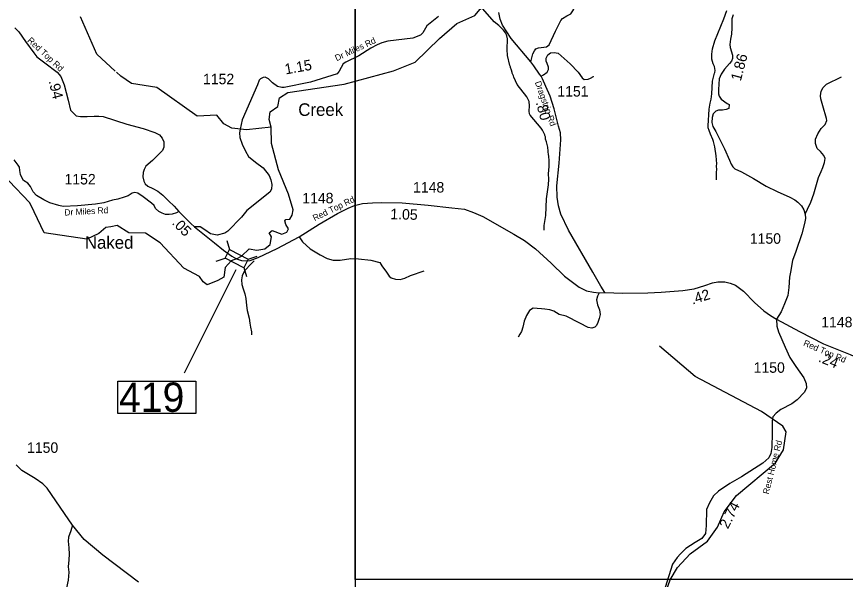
# Model space of a CAD drawing. Extents: x 1248089 to 1457196, y 820910 to 988753.
# Drawn here: x 1308985 to 1318874, y 868837 to 875551 of the extents above; entities that cross this region are included whole.
import ezdxf

# ---------------------------------------------------------------- set-up
doc = ezdxf.new("R2010")
doc.units = 0
for name, color, linetype in [('Exist Hydrographic Creek Single Shore', 7, 'Continuous'), ('Exist Hydrographic Misc Water Feature', 7, 'Continuous'), ('Exist Road Non-System Type 51', 7, 'Continuous'), ('Exist Road Secondary Structure Standard Bridge CELL', 7, 'Continuous'), ('Exist Road Secondary Structure Standard Bridge Number Label', 7, 'Continuous'), ('Exist Road Secondary Type 41 Attributed', 7, 'Continuous'), ('Exist Road Secondary Type 51 Attributed', 7, 'Continuous'), ('Exist Road Secondary Type 51 Label', 7, 'Continuous'), ('Map Preparation Inset Cut Line', 7, 'Continuous'), ('Prop GRAU CAT1 Cell', 7, 'Continuous'), ('Prop Lane Lines', 7, 'Continuous')]:
    doc.layers.add(name, color=color, linetype=linetype)

msp = doc.modelspace()

# ---------------------------------------------------------------- linework, layer by layer
at = {"layer": 'Exist Hydrographic Creek Single Shore'}
for points in [[(1312022.4, 874231.7), (1311999.3, 874324), (1312010.4, 874415.8), (1312103.4, 874479.6), (1312122.3, 874581), (1312223.3, 874644.6), (1312893.3, 874746), (1313480.4, 874905), (1313741.3, 875008.1), (1314032.4, 875289.4), (1314239.5, 875467.5), (1314450.7, 875564.2), (1314515.6, 875637.3), (1314660.8, 875736.4)], [(1312022.4, 874231.7), (1311730.4, 874198.2), (1311555.4, 874218), (1311456.3, 874269.3), (1311375.3, 874372.7), (1311141.4, 874361.1), (1310657.3, 874705.5), (1310358.3, 874754.2), (1310227.2, 874838.9), (1310176.6, 874885.9)], [(1311610.2, 872660.7), (1311668.4, 872691.6), (1311758.7, 872781.3), (1311852.4, 872764.8), (1311948.1, 872778.2), (1312009.9, 872832.8), (1312028.5, 872922.5), (1311999.6, 872971.9), (1312033.5, 872997.4), (1312148.9, 872954.1), (1312210.6, 872977.8), (1312229.2, 873019), (1312199.3, 873070.5), (1312185.9, 873114.9), (1312196.2, 873128.2), (1312244.6, 873132.4), (1312274.5, 873179.8), (1312286.8, 873245.7), (1312228.1, 873430.7), (1312110.3, 873721.1), (1312026.4, 874038), (1312022.4, 874231.7)], [(1309154.5, 873303.6), (1309141.3, 873330.9), (1308897.3, 873588.6), (1308830.3, 873606.4), (1308585.6, 873596.3), (1308575.8, 873602.6), (1308466.6, 873740.7), (1308388.7, 873762), (1308206.5, 873839.3), (1307897, 874073.3)], [(1310982.6, 872548.7), (1310698.4, 872853.2), (1310525.3, 872965.1), (1310325.4, 872969.1), (1310185.3, 873057.2), (1310111.5, 873044.2)], [(1311610.2, 872660.7), (1311545.8, 872635), (1311472.7, 872556.4), (1311459.3, 872441), (1311386.2, 872402.3), (1311258.5, 872348.8), (1311211.2, 872385.9), (1311167.9, 872451.8), (1310982.6, 872548.7)]]:
    msp.add_lwpolyline(points, dxfattribs=at)
at = {"layer": 'Exist Hydrographic Misc Water Feature'}
for points in [[(1315280.9, 873003), (1315278.4, 873059), (1315297.8, 873178.5), (1315309.4, 873378), (1315332.1, 873545.3), (1315333.9, 873609.3), (1315329.8, 873675.3), (1315338.2, 873761), (1315340, 873825), (1315335.8, 873889.1), (1315332, 873897.2), (1315322.7, 873993.5), (1315308.6, 874057.8), (1315297.4, 874090.1), (1315294.1, 874114.2), (1315286.5, 874130.4), (1315286.8, 874138.4), (1315260.4, 874195.2), (1315245.1, 874219.6), (1315113.4, 874375.4), (1315105.9, 874391.6), (1315100.7, 874423.8), (1315106.5, 874487.5), (1315101.9, 874535.6), (1315071.4, 874592.5), (1314959.6, 874739.7), (1314918, 874828.8), (1314914.5, 874844.9), (1314899.4, 874877.4), (1314899.6, 874885.4), (1314888.3, 874909.7), (1314877.2, 874942), (1314877.4, 874950), (1314869.9, 874966.2), (1314843.3, 875087), (1314839.3, 875159.1), (1314840.9, 875286.9), (1314835.8, 875319.1), (1314820.7, 875353.6), (1314793.8, 875390.3), (1314739.2, 875443.9), (1314682.5, 875489.5), (1314548.2, 875641.9)], [(1317336.6, 873603.3), (1317335.3, 873699.3), (1317338, 873723.3), (1317335.3, 873771.3), (1317338, 873795.3), (1317332.6, 873891.3), (1317315.6, 873995.8), (1317301.5, 874060.2), (1317294.1, 874084.4), (1317263.9, 874149.3), (1317249.1, 874189.7), (1317237.9, 874222), (1317234.6, 874246.1), (1317250.2, 874445.6), (1317260.3, 874517.3), (1317271.6, 874564.9), (1317281.4, 874628.6), (1317289.7, 874780.3), (1317312.3, 874875.6), (1317316.5, 874883.5), (1317319.2, 874907.4), (1317310.6, 874955.7), (1317295.5, 874988.1), (1317281.1, 875044.5), (1317280.7, 875100.4), (1317288.4, 875164.2), (1317315.1, 875259.5), (1317422.5, 875522.2), (1317457.4, 875623.2)], [(1310163.5, 874898), (1309941.3, 875104.1), (1309749.3, 875547)], [(1310111.5, 873044.2), (1310051.3, 873033.6), (1309966.3, 872963.1), (1309823.3, 872897), (1309316.3, 872969.6), (1309154.5, 873303.6)], [(1316710, 867717.5), (1316634.5, 868174.3), (1316676.5, 868531.2), (1316783.5, 868831.1), (1316869.5, 868977.1), (1317023.5, 869141.4), (1317227.5, 869294.9), (1317348.5, 869460), (1317427.5, 869642.2), (1317573.5, 869836.2), (1318041.6, 870227.3), (1318136.5, 870382.9), (1318166.6, 870599.1), (1318126.6, 870665.5), (1317872.5, 870838.1), (1317081.5, 871257.7), (1316656.4, 871617.5)]]:
    msp.add_lwpolyline(points, dxfattribs=at)
at = {"layer": 'Exist Road Non-System Type 51'}
for points in [[(1315119.2, 875008.9), (1315143.4, 875106), (1315165.3, 875142.5), (1315182.3, 875164.3), (1315213.8, 875176.5), (1315274.5, 875183.8), (1315308.5, 875191), (1315340, 875215.3), (1315415.3, 875375.6), (1315478.4, 875504.4), (1315497.8, 875528.6), (1315551.2, 875560.2), (1315596.7, 875581.4), (1315623.4, 875617.8), (1315664.7, 875695.5)], [(1315242.1, 874839.3), (1315273.6, 874853.9), (1315314.9, 874887.9), (1315331.9, 874919.5), (1315331.9, 874946.2), (1315317.3, 874989.9), (1315305.2, 875019.1), (1315302.8, 875055.5), (1315322.2, 875094.4), (1315356.1, 875116.2), (1315399.8, 875121.1), (1315445.9, 875113.8), (1315591.6, 874985.1), (1315683.8, 874887.9), (1315732.3, 874819.9), (1315756.6, 874800.5), (1315805.1, 874805.3), (1315831.8, 874815), (1315868.2, 874836.9), (1315869.1, 874841.6)], [(1318394.8, 873191.7), (1318420.6, 873255.1), (1318461.8, 873335.3), (1318495.8, 873437.3), (1318520.1, 873519.9), (1318554.1, 873629.2), (1318585.6, 873704.5), (1318605, 873750.6), (1318624.4, 873811.3), (1318631.7, 873857.5), (1318617.2, 873893.9), (1318578.3, 873940.1), (1318537.1, 873978.9), (1318515.2, 874034.8), (1318517.7, 874088.2), (1318546.8, 874153.8), (1318583.2, 874214.5), (1318631.7, 874263.1), (1318651.1, 874311.7), (1318648.7, 874336), (1318605, 874484.1), (1318580.8, 874570.2), (1318578.3, 874604.2), (1318583.2, 874662.5), (1318607.5, 874703.8), (1318648.7, 874745.1), (1318828.3, 874832.5)], [(1312355.4, 872923.5), (1312396.2, 872863.4), (1312487.2, 872779.6), (1312607.4, 872706.7), (1312691.1, 872666.7), (1312763.9, 872644.8), (1312847.7, 872644.8), (1312971.4, 872666.7), (1313066.1, 872659.4), (1313211.7, 872644.8), (1313317.3, 872615.7), (1313342.8, 872579.2), (1313397.4, 872502.7), (1313430.1, 872455.4), (1313455.6, 872433.5), (1313506.6, 872418.9), (1313561.2, 872415.3), (1313619.4, 872429.9), (1313685, 872462.6), (1313848.8, 872517.3)], [(1311818.7, 872638.8), (1311790.1, 872604.4), (1311705.9, 872515.9), (1311676.4, 872459), (1311670.1, 872408.5), (1311672.2, 872353.7), (1311686.9, 872301), (1311710.1, 872242), (1311720.6, 872189.4), (1311729, 872105.1), (1311737.5, 872044), (1311758.5, 871951.3), (1311766.9, 871892.4), (1311777.5, 871843.9), (1311790.1, 871791.2), (1311790.1, 871753.3)], [(1315935.3, 872256.4), (1315915.4, 872214.9), (1315903.1, 872173.5), (1315916.9, 872113.5), (1315941.5, 872050.5), (1315946.1, 871996.7), (1315935.3, 871947.6), (1315921.5, 871901.5), (1315904.6, 871864.6), (1315883.1, 871844.6), (1315847.8, 871832.3), (1315804.8, 871843.1), (1315705, 871895.3), (1315542.2, 871976.8), (1315457.8, 871998.3), (1315394.8, 872036.7), (1315345.7, 872050.5), (1315288.9, 872061.3), (1315247.4, 872065.9), (1315196.8, 872069), (1315147.6, 872073.6), (1315103.1, 872045.9), (1315069.3, 871986), (1315043.2, 871916.8), (1315026.3, 871844.6), (1315007.9, 871793.9), (1314991, 871763.2), (1314968, 871726.3)], [(1309653.7, 869485.8), (1309633.1, 869416.2), (1309603.1, 869340.1), (1309599.1, 869292.1), (1309607.1, 869212), (1309613.1, 869138), (1309609.1, 869071.9), (1309599.1, 868987.9), (1309607.1, 868921.8), (1309601.1, 868829.7), (1309569.1, 868681.6), (1309571.1, 868545.5), (1309561.3, 868444.7), (1309555.3, 868382.7), (1309537.3, 868300.6), (1309525.3, 868270.6), (1309515.3, 868258.6)]]:
    msp.add_lwpolyline(points, dxfattribs=at)
at = {"layer": 'Exist Road Secondary Structure Standard Bridge CELL'}
for p, q in [((1311492.9, 872879.3), (1311527.4, 872771.5)), ((1311747.5, 872657.4), (1311855.3, 872691.9)), ((1311366.5, 872634.1), (1311474.3, 872668.6)), ((1311695.6, 872556.8), (1311730.1, 872449))]:
    msp.add_line(p, q, dxfattribs=at)
msp.add_lwpolyline([(1311527.4, 872771.5), (1311747.7, 872657.9), (1311694.7, 872555), (1311474.3, 872668.6)], close=True, dxfattribs=at)
at = {"layer": 'Exist Road Secondary Structure Standard Bridge Number Label'}
msp.add_line((1311600, 872528.6), (1310984.4, 871297.5), dxfattribs=at)
msp.add_lwpolyline([(1310194, 871199.9), (1311123, 871199.9), (1311123, 870815.7), (1310194, 870815.7)], close=True, dxfattribs=at)
at = {"layer": 'Exist Road Secondary Type 41 Attributed'}
for points in [[(1314017.3, 875553), (1313878.7, 875440.2), (1313831.7, 875356.6), (1313806, 875328.8), (1313711.8, 875292.4), (1313416.5, 875256), (1313343.7, 875236.7), (1313285.9, 875215.3), (1313211.8, 875173.3), (1313068.4, 875081.2), (1312914.3, 875008.4), (1312880, 874987), (1312835.1, 874901.3), (1312811.6, 874867), (1312493.7, 874769.2), (1312179, 874702.8), (1312149.1, 874702.8), (1312099.9, 874715.6), (1312037.8, 874760.6), (1311990.7, 874807.7), (1311952.2, 874827), (1311926.5, 874822.7), (1311896.5, 874809.8), (1311879.4, 874790.6), (1311860.2, 874737), (1311678.3, 874320.6), (1311653.8, 874206.9), (1311646.2, 874162.1), (1311650.5, 874106.4), (1311676.2, 874027.1), (1311714.7, 873943.6), (1311753.2, 873881.5), (1311834.4, 873813.9), (1311926.4, 873747.5), (1311999.2, 873655.4), (1312020.6, 873604), (1312031.3, 873548.3), (1312027, 873490.5), (1312007.7, 873456.2), (1311734.4, 873238.3), (1311670.2, 873159.1), (1311505.4, 872992), (1311471.2, 872966.3), (1311377, 872942.7), (1311297.8, 872957.7), (1311231.5, 873007), (1311173.7, 873043.4), (1311109.5, 873043.4)], [(1310921.8, 873226), (1310893.3, 873208.4), (1310843.5, 873193.3), (1310805.5, 873187.8), (1310763.4, 873190.6), (1310722.8, 873206.9), (1310683.4, 873225.9), (1310644.1, 873261.1), (1310625.1, 873296.4), (1310595.2, 873325), (1310494.9, 873402.3), (1310433.8, 873443.1), (1310395.9, 873452.6), (1310362.5, 873443.1), (1310316.4, 873413.3), (1310270.3, 873395.6), (1310191.6, 873372.6), (1310127.9, 873361.7), (1310026.1, 873327.8), (1309927.1, 873312.8), (1309713.5, 873293.7), (1309542.6, 873287), (1309491, 873297.8), (1309381.2, 873329), (1309309.3, 873364.3), (1309223.8, 873417.3), (1309184.5, 873459.4), (1309153.3, 873524.5), (1309118.3, 873561.8), (1309068.1, 873597.1), (1309047.8, 873629.6), (1309032.9, 873666.3), (1309026.1, 873713.8), (1309020.6, 873754.5), (1309005.7, 873779), (1308956.9, 873842.8)], [(1318052.7, 871939.5), (1318056.1, 871858.6), (1318074.3, 871790.9), (1318156.1, 871605.9), (1318209.2, 871484.8), (1318281.8, 871375.8), (1318379.1, 871240.5), (1318405.5, 871174.5), (1318408.8, 871123.3), (1318385.7, 871072.1), (1318298.3, 870979.7), (1318232.8, 870931.1), (1318104.2, 870865.1), (1318048.1, 870820.5), (1318006.9, 870774.3), (1317998.6, 870729.7)], [(1317998.6, 870729.7), (1317998.6, 870583.5), (1317995.3, 870410.2), (1317985.4, 870337.6), (1317959, 870288.1), (1317888.6, 870224.2), (1317634.6, 870059.2), (1317496, 869981.6), (1317359.6, 869890), (1317298.5, 869832.2), (1317252.4, 869749.7), (1317217.7, 869668.8), (1317214.4, 869480.6), (1317203.3, 869382.6), (1317160.4, 869324.8), (1317082.9, 869275.3), (1316969.1, 869204.3), (1316906.4, 869143.3), (1316866.9, 869097), (1316812.4, 869019.5), (1316725.4, 868740.2)], [(1310441.6, 868803.4), (1310014.9, 869126), (1309792.2, 869312.5), (1309653.7, 869485.8), (1309556.8, 869621.9), (1309349, 869924), (1309299.5, 869978.4), (1309205.5, 870039.5), (1309047.2, 870136.9), (1308981.2, 870204.6)]]:
    msp.add_lwpolyline(points, dxfattribs=at)
at = {"layer": 'Exist Road Secondary Type 51 Attributed'}
for points in [[(1316003.9, 872258.2), (1315956.7, 872335.8), (1315860.3, 872500.7), (1315569.6, 873002.8), (1315479.8, 873195.5), (1315449.8, 873291.9), (1315434.8, 873394.7), (1315432.6, 873532.9), (1315460.5, 873800.6), (1315477.6, 874079.1), (1315473.3, 874164.7), (1315452, 874242.8), (1315398.5, 874448.4), (1315349.5, 874599.5), (1315300.3, 874717.3), (1315259.6, 874809.4), (1315242.1, 874839.3), (1315223.2, 874865.1), (1315154.7, 874963.6), (1315119.2, 875008.9), (1314885.4, 875290.1), (1314782.7, 875448.6), (1314754.8, 875521.4), (1314737.7, 875598.5)], [(1317534, 875571.9), (1317517.3, 875524.3), (1317517.3, 875416.7), (1317515.9, 875339.8), (1317504.7, 875279.7), (1317496.3, 875216.8), (1317499.2, 875182.6), (1317525.7, 875091.8), (1317525.7, 875051.2), (1317514.5, 875020.5), (1317489.4, 874991.1), (1317432.1, 874922.6), (1317390.2, 874863.9), (1317369.3, 874808), (1317359.5, 874682), (1317359.5, 874627.5), (1317366.5, 874600.9), (1317393.1, 874567.4), (1317462.9, 874512.9), (1317485.3, 874500.3), (1317481.1, 874455.6), (1317451.7, 874441.6), (1317405.6, 874436), (1317360.9, 874436), (1317327.4, 874423.4), (1317296.7, 874391.3), (1317282.7, 874346.5), (1317279.9, 874286.4), (1317292.5, 874238.9), (1317327.3, 874179.5), (1317432, 873974), (1317492.1, 873838.4), (1317510.2, 873790.9), (1317531.2, 873758.7), (1317556.3, 873735), (1317635.2, 873697.9), (1317776.3, 873621), (1317927.2, 873528.8), (1318059.6, 873462.1), (1318209, 873396.4), (1318269.1, 873364.2), (1318308.2, 873337.7), (1318351.5, 873294.3), (1318379.4, 873246.2), (1318394.8, 873191.7), (1318396.2, 873141.3), (1318387.8, 873081.2), (1318352.9, 872958.2), (1318281.6, 872747.1), (1318242.7, 872642), (1318220.3, 872503.6), (1318205, 872442.1), (1318200.8, 872317.7), (1318185.4, 872225.4), (1318147.7, 872124), (1318108.6, 872029), (1318052.7, 871939.5)], [(1308962.9, 875417.3), (1309013.1, 875368.5), (1309091.7, 875253.6), (1309189.3, 875119.2), (1309226, 875071.7), (1309320.6, 874997.7), (1309469.8, 874887.8), (1309513.2, 874834.8), (1309553.2, 874737.7), (1309599.3, 874551.7), (1309630.5, 874435), (1309667.1, 874394.3), (1309694.3, 874368.5), (1309749.9, 874357.6), (1309827.2, 874359), (1309911.3, 874361.7), (1309968.3, 874364.4), (1310018.4, 874359), (1310302.4, 874268.6), (1310496.3, 874215.6), (1310636.1, 874168.1), (1310691.7, 874141), (1310722.9, 874100.2), (1310741.9, 874056.8), (1310743.2, 873994.3), (1310726.9, 873952.3), (1310607.8, 873832.5), (1310529.2, 873764.6), (1310507.5, 873725.2), (1310495.2, 873692.6), (1310492.5, 873638.3), (1310502, 873586.7), (1310521, 873554.2), (1310550.9, 873528.4), (1310611.9, 873498.5), (1310670.2, 873468.6), (1310729.9, 873421.1), (1310796.4, 873351.9), (1310865.5, 873290.8), (1310921.8, 873226)], [(1311610.2, 872660.7), (1311669.1, 872641.2), (1311728.8, 872637), (1311771, 872642.2), (1311865.8, 872675.2), (1312094.3, 872784.3), (1312355.4, 872923.5), (1312595.1, 873075.6), (1312815.5, 873202), (1312940.3, 873266), (1313015.2, 873296), (1313111.5, 873319.5), (1313233.5, 873330.2), (1313344.8, 873334.5), (1313584.5, 873328.1), (1313897, 873300.2), (1314176.4, 873270.2), (1314328.3, 873253.1), (1314437.5, 873212.4), (1314546.6, 873165.2), (1314916.9, 872953.2), (1315046.8, 872878.4), (1315177.4, 872782), (1315361.5, 872610.7), (1315523.5, 872454.9), (1315632.7, 872371.4), (1315696.9, 872324.3), (1315785.3, 872278.3), (1315867.4, 872263.3), (1315935.3, 872256.4), (1316003.9, 872258.2)], [(1310921.8, 873226), (1311064.6, 873084.1), (1311109.5, 873043.4)], [(1311109.5, 873043.4), (1311347.8, 872853.4), (1311452.8, 872764.8), (1311553.7, 872693.7), (1311610.2, 872660.7)], [(1316003.9, 872258.2), (1316217.7, 872253.2), (1316516.1, 872255.7), (1316677.7, 872263.1), (1316934.6, 872284.4), (1317068, 872302.9), (1317194.8, 872342.8), (1317286.8, 872375.1), (1317352.8, 872385.1), (1317434.9, 872385.1), (1317499.5, 872370.2), (1317561.7, 872347.8), (1317658.6, 872275.7), (1317787.9, 872141.3), (1317899.8, 872041.8), (1317979.4, 871984.5), (1318052.7, 871939.5)], [(1318052.7, 871939.5), (1318326.1, 871792.7), (1318611.3, 871648.5), (1318928.9, 871519), (1319221.9, 871390)]]:
    msp.add_lwpolyline(points, dxfattribs=at)
at = {"layer": 'Map Preparation Inset Cut Line'}
for points in [[(1313026.2, 913085.2), (1388709.5, 913085.2), (1388709.5, 884379.9), (1373500.6, 884376.6), (1373500.6, 868836.7), (1313026.2, 868836.7)], [(1313026.2, 867658.5), (1300766.9, 867658.5), (1300766.9, 889680.3), (1313026.2, 889680.3)]]:
    msp.add_lwpolyline(points, close=True, dxfattribs=at)

# ---------------------------------------------------------------- texts
at = {"layer": 'Exist Hydrographic Creek Single Shore'}
for s, p in [('Creek', (1312346.2, 874365.8)), ('Naked', (1309799.8, 872781.1))]:
    msp.add_text(s, height=150, dxfattribs=at).set_placement(p)
at = {"layer": 'Exist Road Secondary Structure Standard Bridge Number Label'}
msp.add_text('419', height=350, dxfattribs=at).set_placement((1310206.6, 870835.5))
at = {"layer": 'Exist Road Secondary Type 51 Label'}
for s, rotation, p in [('Red Top Rd', 316.9684, (1309108.7, 875258)), ('Dr Miles Rd', 25.04822, (1312804.4, 875017.1)), ('Dragstrip Rd', 289.63294, (1315167.6, 874765.7)), ('Red Top Rd', 25.92932, (1312541.3, 873108.9)), ('Dr Miles Rd', 3.17803, (1309558.2, 873176.1)), ('Red Top Rd', 336.93288, (1318365.6, 871628.9)), ('Rest Home Rd', 75.78475, (1317958.9, 869847.7))]:
    msp.add_text(s, height=75, rotation=rotation, dxfattribs=at).set_placement(p)
at = {"layer": 'Prop GRAU CAT1 Cell'}
for s, rotation, p in [('1.86', 75.22104, (1317625.4, 874773.9)), ('1.15', 10.13271, (1312195.5, 874859.9)), ('.94', 283.92703, (1309366.2, 874780.8)), ('.80', 285.2541, (1315178.9, 874525)), ('1.05', 358.46426, (1313443.5, 873133.9)), ('.05', 315.16574, (1310831.3, 873081)), ('.42', 17.43085, (1317049.5, 872114.5)), ('.24', 337.81797, (1318543.4, 871437.8)), ('2.74', 63.064, (1317472.3, 869431.6))]:
    msp.add_text(s, height=125, rotation=rotation, dxfattribs=at).set_placement(p)
at = {"layer": 'Prop Lane Lines'}
for s, p in [('1152', (1311209.7, 874743.4)), ('1151', (1315437.2, 874596.5)), ('1152', (1309557.5, 873548.1)), ('1148', (1313715.8, 873451.9)), ('1148', (1312394.3, 873322.9)), ('1150', (1317733.8, 872840.7)), ('1148', (1318585.7, 871843.5)), ('1150', (1317779.1, 871301.4)), ('1150', (1309110.5, 870346.4))]:
    msp.add_text(s, height=125, dxfattribs=at).set_placement(p)

doc.saveas('drawing.dxf')
